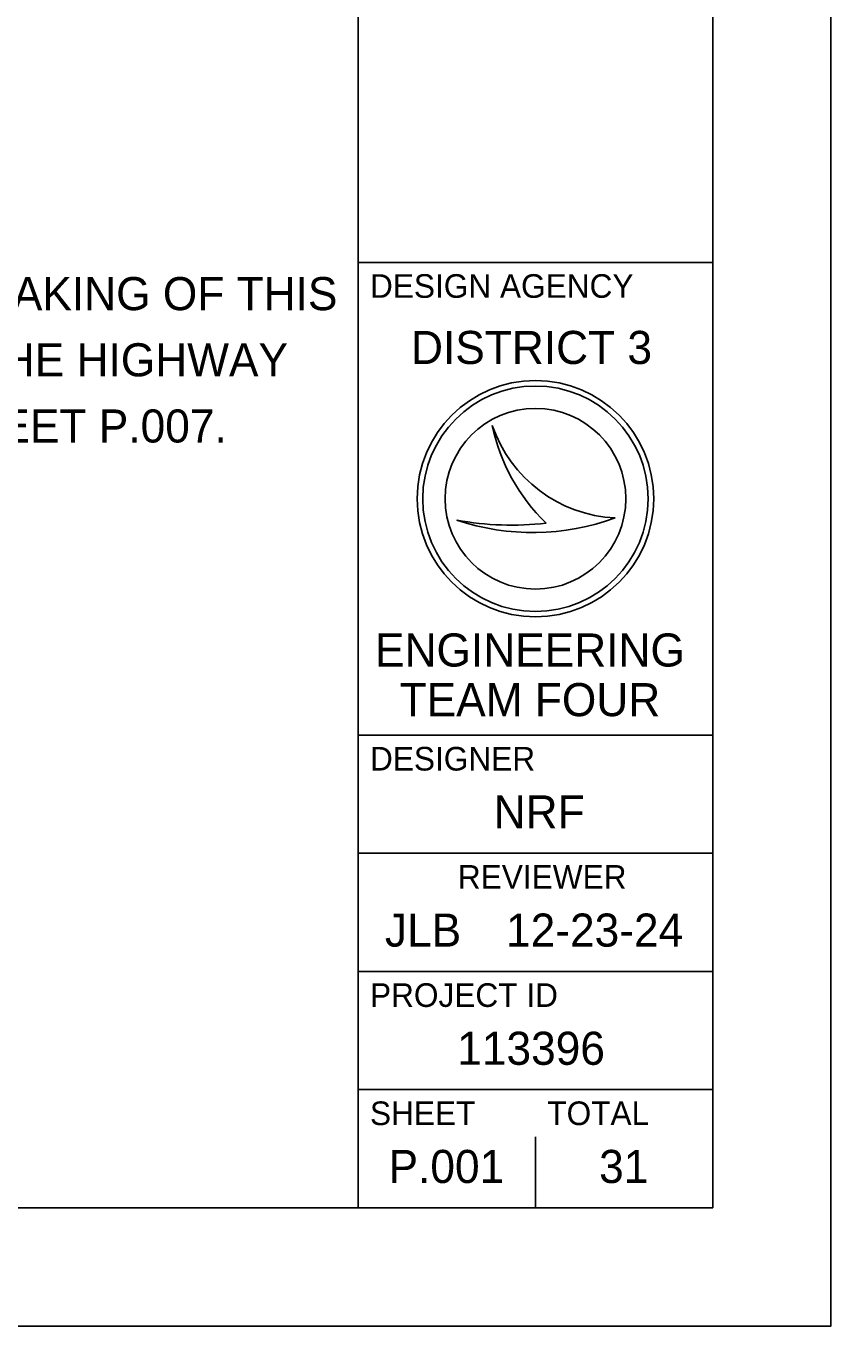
# Model space of a CAD drawing. Extents: x -21.1 to 50.3, y -4.9 to 22.1.
# Drawn here: x 30.6 to 34, y 0 to 5.5 of the extents above; entities that cross this region are included whole.
import ezdxf

# ---------------------------------------------------------------- set-up
doc = ezdxf.new("R2010")
doc.units = 0
for name, color, linetype in [('SH_Border', 7, 'Continuous'), ('SH_Cut_Line', 7, 'Continuous'), ('SH_Data', 7, 'Continuous')]:
    doc.layers.add(name, color=color, linetype=linetype)

msp = doc.modelspace()

# ---------------------------------------------------------------- linework, layer by layer
at = {"layer": 'SH_Border'}
for p, q in [((32, 0.5), (32, 21.5)), ((32, 4.5), (33.5, 4.5)), ((32, 2.5), (33.5, 2.5)), ((32, 2), (33.5, 2)), ((32, 1.5), (33.5, 1.5)), ((32, 1), (33.5, 1))]:
    msp.add_line(p, q, dxfattribs=at)
msp.add_lwpolyline([(1.5, 21.5), (33.5, 21.5), (33.5, 0.5), (1.5, 0.5)], close=True, dxfattribs=at)
at = {"layer": 'SH_Cut_Line'}
msp.add_lwpolyline([(0, 0), (34, 0), (34, 22), (0, 22)], close=True, dxfattribs=at)
at = {"layer": 'SH_Data'}
for p, q in [((32.5674, 3.8096), (32.5675, 3.8096)), ((32.75, 3.5), (32.75, 3.5)), ((33.0873, 3.4185), (33.0873, 3.4185)), ((32.4172, 3.4095), (32.4172, 3.4095)), ((32.75, 0.5), (32.75, 0.8)), ((32.375, 0.675), (32.375, 0.675))]:
    msp.add_line(p, q, dxfattribs=at)
for radius in [0.5, 0.4768, 0.4768, 0.3822]:
    msp.add_circle((32.75, 3.5), radius, dxfattribs=at)
for centre, radius, start, end in [((33.1159, 3.9976), 0.5798, 198.9257, 198.9319), ((33.3467, 3.9701), 0.7956, 191.6379, 191.6421), ((33.1159, 3.9976), 0.5798, 198.9319, 267.1657), ((33.3467, 3.9701), 0.7956, 191.6421, 226.0947), ((32.7394, 4.37), 1.0131, 251.4576, 290.0832), ((32.648, 4.6543), 1.2661, 259.4964, 259.4995), ((32.7394, 4.37), 1.0131, 251.4527, 251.4576), ((32.648, 4.6543), 1.2661, 259.4995, 276.6672)]:
    msp.add_arc(centre, radius, start, end, dxfattribs=at)

# ---------------------------------------------------------------- texts
for s, height, p in [(' I HEREBY APPROVE THESE PLANS AND DECLARE THAT THE MAKING OF THIS', 0.14, (24.7553, 4.2977)), ('DESIGN AGENCY', 0.1, (32.05, 4.35)), ('DISTRICT 3', 0.14, (32.2237, 4.07)), ('IMPROVEMENT WILL REQUIRE THE CLOSING TO TRAFFIC OF THE HIGHWAY', 0.14, (24.7553, 4.0177)), ('AND THAT DETOURS WILL BE PROVIDED AS INDICATED ON SHEET P.007.', 0.14, (24.7553, 3.7377)), ('ENGINEERING', 0.14, (32.0713, 2.79)), ('TEAM FOUR', 0.14, (32.1753, 2.58)), ('DESIGNER', 0.1, (32.05, 2.35)), ('NRF', 0.14, (32.5731, 2.105)), ('REVIEWER', 0.1, (32.4218, 1.85)), ('JLB', 0.14, (32.1133, 1.605)), ('12-23-24', 0.14, (32.6254, 1.605)), ('PROJECT ID', 0.1, (32.05, 1.35)), ('113396', 0.14, (32.4191, 1.105)), ('SHEET', 0.1, (32.05, 0.85)), ('TOTAL', 0.1, (32.8, 0.85)), ('P.001', 0.14, (32.1285, 0.605)), ('31', 0.14, (33.0192, 0.605))]:
    msp.add_text(s, height=height, dxfattribs=at).set_placement(p)

doc.saveas('drawing.dxf')
